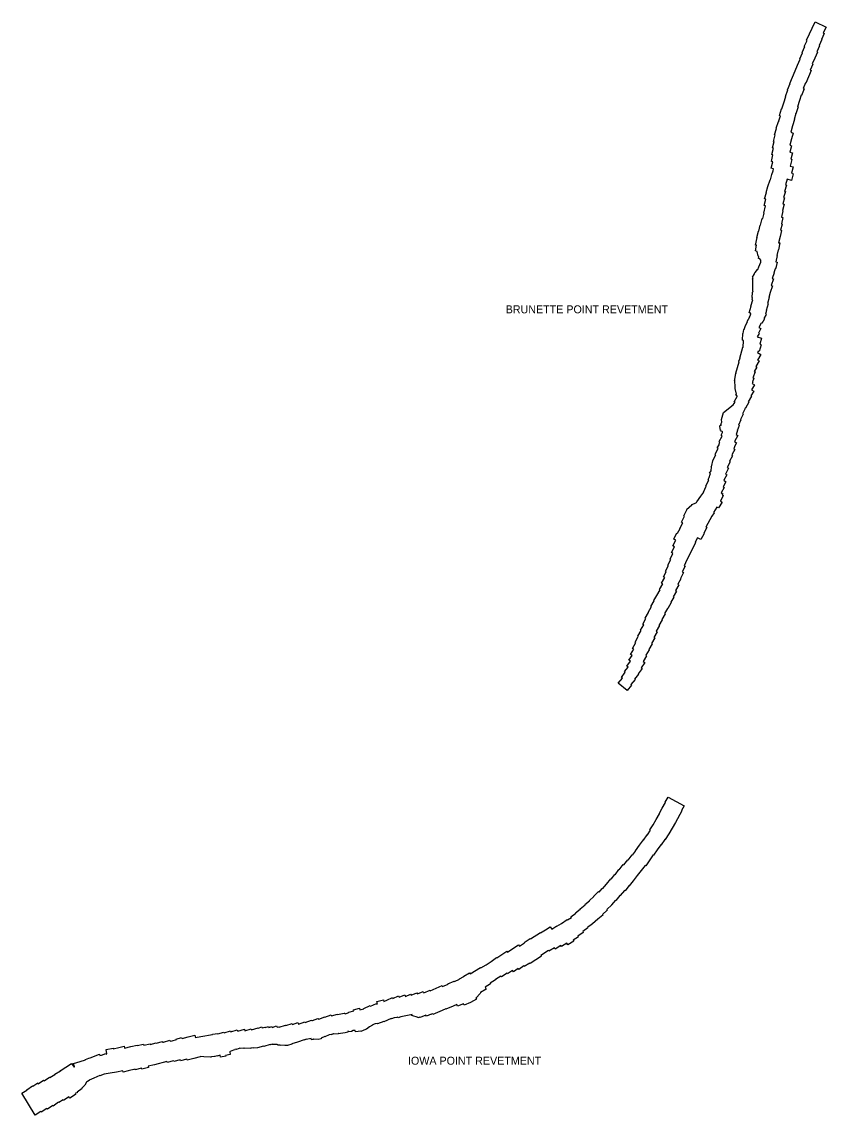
# Model space of a CAD drawing. Extents: x 2650582 to 3923188, y 277893 to 989177.
# Drawn here: x 3203021 to 3219097, y 825723 to 847578 of the extents above; entities that cross this region are included whole.
import ezdxf

# ---------------------------------------------------------------- set-up
doc = ezdxf.new("R2010")
doc.units = 0
doc.layers.add('Level 3', color=7, linetype='Continuous')

msp = doc.modelspace()

# ---------------------------------------------------------------- linework, layer by layer
at = {"layer": 'Level 3'}
for points in [[(3218284, 846087), (3218329, 846216), (3218328, 846216), (3218377, 846343), (3218369, 846346), (3218424, 846475), (3218425, 846475), (3218478, 846596), (3218480, 846596), (3218528, 846709), (3218525, 846710), (3218579, 846835), (3218570, 846840), (3218626, 846959), (3218615, 846964), (3218671, 847084), (3218661, 847088), (3218717, 847208), (3218706, 847213), (3218765, 847341), (3218768, 847339), (3218820, 847450), (3218817, 847451), (3218877, 847578), (3219097, 847475), (3219041, 847356), (3219060, 847346), (3219005, 847228), (3219012, 847224), (3218956, 847104), (3218968, 847099), (3218913, 846979), (3218926, 846974), (3218870, 846854), (3218874, 846852), (3218820, 846736), (3218832, 846730), (3218781, 846609), (3218797, 846603), (3218746, 846481), (3218746, 846481), (3218692, 846352), (3218682, 846356), (3218637, 846247), (3218655, 846240), (3218606, 846109), (3218598, 846112), (3218562, 846005)], [(3218038, 844603), (3218048, 844640), (3218000, 844653), (3218034, 844780), (3218002, 844789), (3218035, 844917), (3218009, 844924), (3218042, 845052), (3218024, 845057), (3218058, 845184), (3218045, 845187), (3218079, 845319), (3218068, 845321), (3218107, 845448), (3218100, 845450), (3218142, 845583), (3218147, 845582), (3218183, 845699), (3218168, 845704), (3218208, 845838), (3218213, 845837), (3218251, 845962), (3218252, 845962), (3218289, 846085), (3218284, 846087)], [(3218562, 846005), (3218564, 846005), (3218527, 845879), (3218535, 845876), (3218494, 845742), (3218491, 845743), (3218456, 845626), (3218465, 845623), (3218426, 845497), (3218427, 845497), (3218389, 845371), (3218437, 845356), (3218402, 845238), (3218406, 845237), (3218372, 845110), (3218407, 845100), (3218373, 844972), (3218424, 844958), (3218390, 844830), (3218413, 844824), (3218379, 844696), (3218437, 844681), (3218404, 844553), (3218441, 844543), (3218405, 844408), (3218321, 844431)], [(3217790, 842811), (3217771, 842844), (3217747, 842850), (3217753, 842881), (3217744, 842892), (3217739, 842891), (3217718, 842990), (3217683, 842998), (3217708, 843111), (3217687, 843115), (3217718, 843264), (3217712, 843265), (3217745, 843395), (3217753, 843393), (3217782, 843512), (3217786, 843511), (3217820, 843649), (3217831, 843647), (3217856, 843752), (3217849, 843753), (3217885, 843899), (3217858, 843907), (3217891, 844033), (3217864, 844041), (3217903, 844165), (3217896, 844167), (3217935, 844287), (3217933, 844288), (3217978, 844423), (3217982, 844421), (3218013, 844524), (3218012, 844524), (3218038, 844603)], [(3218321, 844431), (3218288, 844318), (3218308, 844311), (3218267, 844190), (3218284, 844184), (3218246, 844067), (3218268, 844060), (3218230, 843941), (3218258, 843933), (3218224, 843806), (3218235, 843803), (3218203, 843677), (3218235, 843669), (3218204, 843541), (3218219, 843537), (3218188, 843413), (3218207, 843408), (3218177, 843285), (3218177, 843285), (3218146, 843163), (3218173, 843158), (3218145, 843020), (3218137, 843021), (3218112, 842909), (3218120, 842907), (3218091, 842781), (3218118, 842775), (3218098, 842688)], [(3217561, 841761), (3217597, 841893), (3217593, 841894), (3217629, 842022), (3217616, 842025), (3217627, 842064), (3217620, 842065), (3217628, 842170), (3217636, 842199), (3217632, 842199), (3217635, 842435), (3217628, 842437), (3217639, 842469), (3217628, 842475), (3217656, 842529), (3217659, 842527), (3217674, 842569), (3217680, 842567), (3217680, 842567), (3217727, 842629), (3217731, 842627), (3217750, 842684), (3217754, 842683), (3217791, 842776), (3217789, 842811), (3217790, 842811)], [(3218098, 842688), (3218099, 842688), (3218096, 842681), (3218087, 842641), (3218081, 842642), (3218049, 842564), (3218056, 842559), (3218019, 842448), (3218043, 842439), (3217997, 842308), (3218023, 842300), (3217978, 842166), (3217950, 842069), (3217957, 842067), (3217923, 841947), (3217938, 841943), (3217900, 841811), (3217905, 841810), (3217885, 841736)], [(3217010, 839577), (3217007, 839627), (3217048, 839767), (3217047, 839768), (3217240, 839923), (3217276, 839975), (3217259, 839985), (3217319, 840087), (3217316, 840101), (3217294, 840114), (3217307, 840137), (3217281, 840248), (3217286, 840249), (3217276, 840249), (3217276, 840275), (3217274, 840276), (3217276, 840279), (3217275, 840404), (3217265, 840410), (3217275, 840427), (3217275, 840437), (3217275, 840437), (3217289, 840546), (3217295, 840545), (3217301, 840557), (3217295, 840558), (3217359, 840784), (3217350, 840790), (3217352, 840794), (3217379, 840856), (3217374, 840857), (3217431, 841072), (3217442, 841069), (3217444, 841206), (3217433, 841210), (3217435, 841216), (3217426, 841217), (3217435, 841351), (3217440, 841351), (3217453, 841427), (3217462, 841426), (3217458, 841428), (3217482, 841490), (3217476, 841493), (3217524, 841584), (3217520, 841586), (3217571, 841678), (3217564, 841681), (3217589, 841731), (3217583, 841733), (3217589, 841753), (3217561, 841761)], [(3217885, 841736), (3217896, 841730), (3217853, 841647), (3217864, 841642), (3217814, 841546), (3217802, 841553), (3217753, 841465), (3217790, 841446), (3217743, 841354), (3217756, 841347), (3217719, 841279)], [(3217719, 841279), (3217803, 841255)], [(3217803, 841255), (3217769, 841133), (3217800, 841124), (3217761, 840987), (3217738, 840993)], [(3217738, 840993), (3217725, 840969), (3217794, 840926), (3217727, 840818), (3217759, 840799), (3217691, 840690), (3217712, 840677), (3217661, 840591), (3217678, 840585), (3217634, 840459), (3217649, 840454), (3217623, 840380), (3217634, 840374), (3217618, 840346)], [(3217618, 840346), (3217663, 840319), (3217605, 840224), (3217650, 840197), (3217592, 840101), (3217606, 840093), (3217542, 839983), (3217555, 839975), (3217483, 839853), (3217478, 839856), (3217470, 839841), (3217475, 839838), (3217424, 839745), (3217440, 839734), (3217386, 839628), (3217395, 839622), (3217345, 839516), (3217356, 839506), (3217338, 839458)], [(3216813, 838708), (3216830, 838806), (3216834, 838805), (3216831, 838807), (3216891, 838923), (3216881, 838929), (3216884, 838934), (3216880, 838936), (3216941, 839050), (3216921, 839062), (3216956, 839121), (3216966, 839171), (3216971, 839184), (3216960, 839191), (3217022, 839299), (3216997, 839314), (3217028, 839369), (3217028, 839385), (3217019, 839388), (3217018, 839390), (3216993, 839399), (3216996, 839407), (3216985, 839406), (3216974, 839493), (3216980, 839515), (3217002, 839518), (3217006, 839528), (3216993, 839533), (3217010, 839577)], [(3217338, 839458), (3217341, 839457), (3217323, 839420), (3217320, 839413), (3217327, 839410), (3217298, 839329), (3217331, 839311), (3217267, 839186), (3217307, 839165), (3217275, 839104), (3217252, 839041), (3217271, 839031), (3217222, 838939), (3217211, 838912), (3217227, 838904), (3217169, 838793)], [(3217169, 838793), (3217182, 838785), (3217119, 838668), (3217145, 838653), (3217083, 838539), (3217111, 838524), (3217053, 838419), (3217095, 838384), (3217041, 838280), (3217057, 838272), (3217001, 838160), (3217035, 838144), (3217022, 838117)], [(3216650, 838176), (3216645, 838179), (3216702, 838296), (3216694, 838300), (3216751, 838414), (3216743, 838416), (3216746, 838424), (3216737, 838428), (3216758, 838469), (3216776, 838533), (3216777, 838533), (3216783, 838545), (3216767, 838554), (3216796, 838606), (3216808, 838681), (3216801, 838686), (3216813, 838708)], [(3216507, 837970), (3216515, 837981), (3216592, 838096), (3216596, 838094), (3216650, 838176)], [(3216176, 837449), (3216236, 837563), (3216205, 837580), (3216265, 837696), (3216250, 837704), (3216313, 837821), (3216307, 837828), (3216411, 837923), (3216409, 837925), (3216507, 837970)], [(3217022, 838117), (3217039, 838108), (3216986, 837996), (3217019, 837974), (3216943, 837860), (3216915, 837878), (3216843, 837772), (3216858, 837761), (3216810, 837695)], [(3216810, 837695), (3216693, 837479), (3216712, 837469), (3216652, 837355), (3216659, 837351), (3216594, 837229), (3216525, 837266)], [(3215660, 836007), (3215656, 836009), (3215716, 836112), (3215714, 836112), (3215779, 836225), (3215767, 836232), (3215832, 836345), (3215808, 836358), (3215873, 836471), (3215846, 836486), (3215903, 836586), (3215888, 836594), (3215946, 836708), (3215935, 836714), (3215995, 836829), (3215977, 836839), (3216036, 836953), (3216009, 836967), (3216069, 837083), (3216032, 837102), (3216091, 837216), (3216051, 837236), (3216115, 837361), (3216129, 837354), (3216178, 837449), (3216176, 837449)], [(3216525, 837266), (3216479, 837176), (3216489, 837171), (3216431, 837056), (3216433, 837055), (3216315, 836823), (3216316, 836823), (3216257, 836707), (3216278, 836696), (3216219, 836583), (3216244, 836570), (3216185, 836453), (3216196, 836446), (3216131, 836334), (3216150, 836323), (3216085, 836210), (3216107, 836197), (3216042, 836086), (3216053, 836079), (3215993, 835976), (3216001, 835971)], [(3216001, 835971), (3215930, 835851), (3215924, 835853), (3215864, 835749), (3215877, 835741), (3215813, 835630), (3215820, 835625), (3215756, 835514), (3215766, 835508), (3215702, 835397), (3215721, 835384), (3215656, 835272), (3215670, 835264), (3215605, 835151), (3215621, 835142), (3215555, 835028), (3215557, 835027), (3215492, 834915), (3215507, 834906), (3215441, 834792), (3215471, 834772), (3215397, 834665), (3215417, 834650), (3215341, 834547), (3215349, 834540), (3215268, 834439), (3215277, 834431), (3215195, 834330), (3215210, 834319), (3215121, 834210), (3214941, 834356), (3215024, 834456), (3215005, 834472), (3215081, 834577), (3215068, 834589), (3215140, 834677), (3215113, 834697), (3215185, 834796), (3215154, 834816), (3215218, 834911), (3215186, 834929), (3215251, 835041), (3215229, 835054), (3215296, 835168), (3215278, 835178), (3215343, 835290), (3215333, 835296), (3215399, 835408), (3215387, 835415), (3215452, 835527), (3215430, 835540), (3215494, 835650), (3215480, 835659), (3215545, 835770), (3215539, 835774), (3215605, 835888), (3215595, 835893), (3215660, 836007)], [(3214794, 830444), (3214800, 830440), (3214872, 830535), (3214881, 830529), (3214956, 830631), (3214958, 830630), (3215037, 830735), (3215053, 830724), (3215133, 830829), (3215142, 830823), (3215219, 830924), (3215228, 830917), (3215288, 831003), (3215284, 831006), (3215365, 831120), (3215368, 831117), (3215444, 831224), (3215446, 831222), (3215520, 831327), (3215524, 831325), (3215585, 831418), (3215573, 831426), (3215640, 831529), (3215703, 831632), (3215702, 831633), (3215764, 831747), (3215763, 831747), (3215823, 831858), (3215887, 831976), (3215883, 831978), (3215939, 832082), (3216258, 831907), (3216204, 831810), (3216214, 831805), (3216085, 831571), (3216083, 831572), (3216020, 831457), (3216017, 831458), (3215951, 831348), (3215952, 831347), (3215877, 831230), (3215871, 831233), (3215801, 831124), (3215792, 831129), (3215723, 831029), (3215648, 830922), (3215642, 830926), (3215491, 830707), (3215480, 830715), (3215402, 830611), (3215398, 830614), (3215321, 830513), (3215319, 830514), (3215240, 830408), (3215238, 830410), (3215159, 830305), (3215155, 830308), (3215079, 830204)], [(3213612, 829444), (3213713, 829507), (3213717, 829499), (3213808, 829554), (3213806, 829556), (3213923, 829633), (3213929, 829625), (3214005, 829677), (3213996, 829690), (3214093, 829761), (3214086, 829770), (3214181, 829842), (3214178, 829845), (3214279, 829928), (3214275, 829933), (3214366, 830009), (3214364, 830011), (3214454, 830092), (3214449, 830097), (3214550, 830193), (3214561, 830182), (3214623, 830254), (3214630, 830248), (3214707, 830339), (3214708, 830339), (3214794, 830444)], [(3215079, 830204), (3215064, 830215), (3214977, 830111), (3214976, 830112), (3214894, 830014), (3214886, 830019), (3214808, 829927), (3214811, 829924), (3214715, 829832), (3214723, 829822), (3214625, 829734), (3214635, 829723), (3214535, 829641), (3214537, 829638), (3214429, 829548), (3214427, 829550), (3214327, 829472), (3214332, 829466), (3214231, 829394), (3214242, 829377), (3214137, 829303), (3214146, 829290), (3214042, 829222), (3214053, 829204), (3213935, 829130), (3213917, 829159), (3213806, 829091), (3213794, 829111), (3213683, 829043), (3213666, 829070), (3213554, 829001), (3213547, 829013)], [(3212836, 829054), (3212949, 829127), (3212968, 829099), (3213071, 829166), (3213064, 829177), (3213184, 829254), (3213190, 829245), (3213386, 829373), (3213391, 829366), (3213486, 829430), (3213489, 829427), (3213582, 829490), (3213612, 829444)], [(3211419, 828316), (3211428, 828295), (3211540, 828343), (3211538, 828349), (3211663, 828403), (3211666, 828396), (3211770, 828440), (3211766, 828450), (3211855, 828496), (3211852, 828504), (3211968, 828568), (3211979, 828549), (3212190, 828675), (3212193, 828670), (3212299, 828731), (3212302, 828727), (3212403, 828792), (3212401, 828796), (3212511, 828872), (3212516, 828865), (3212712, 829003), (3212726, 828983), (3212836, 829055), (3212836, 829054)], [(3213547, 829013), (3213394, 828915), (3213405, 828898), (3213179, 828752), (3213172, 828764), (3213062, 828695), (3213055, 828707)], [(3213055, 828707), (3212953, 828637), (3212940, 828653), (3212847, 828589), (3212828, 828613), (3212731, 828547), (3212719, 828563), (3212606, 828488), (3212598, 828498), (3212489, 828432), (3212491, 828428), (3212381, 828360), (3212389, 828348), (3212279, 828280), (3212302, 828242), (3212188, 828174), (3212190, 828171), (3212182, 828166), (3212191, 828159), (3212097, 828059), (3212107, 828040), (3211989, 827976), (3211860, 827920), (3211847, 827950), (3211728, 827901), (3211714, 827932), (3211644, 827904), (3211645, 827902), (3211497, 827843), (3211495, 827847), (3211423, 827817), (3211237, 827733)], [(3210688, 828098), (3210792, 828143), (3210802, 828123), (3210917, 828171), (3210928, 828145), (3211045, 828195), (3211057, 828169), (3211179, 828221), (3211185, 828207), (3211419, 828316)], [(3209859, 827851), (3209858, 827854), (3209986, 827912), (3209991, 827903), (3210109, 827955), (3210116, 827944), (3210129, 827950), (3210116, 827993), (3210247, 828031), (3210259, 827993), (3210319, 828019), (3210318, 828022), (3210432, 828072), (3210439, 828058), (3210551, 828107), (3210564, 828079), (3210674, 828128), (3210688, 828098)], [(3208540, 827574), (3208552, 827543), (3208679, 827589), (3208685, 827576), (3208808, 827621), (3208813, 827610), (3208818, 827612), (3208818, 827613), (3208828, 827615), (3208939, 827657), (3208942, 827646), (3208953, 827649), (3208954, 827644), (3209075, 827691), (3209079, 827682), (3209200, 827729), (3209207, 827711), (3209332, 827740), (3209333, 827737), (3209460, 827762), (3209461, 827759), (3209473, 827764), (3209480, 827751), (3209503, 827755), (3209555, 827776), (3209554, 827782), (3209657, 827806), (3209651, 827828), (3209771, 827860), (3209779, 827829), (3209859, 827851)], [(3210820, 827735), (3210796, 827727), (3210593, 827691), (3210543, 827670), (3210538, 827681), (3210518, 827673), (3210516, 827678), (3210464, 827669), (3210410, 827646), (3210406, 827655), (3210256, 827590), (3210253, 827598), (3210132, 827545), (3210123, 827558), (3210081, 827546), (3210081, 827548), (3210029, 827526), (3210032, 827520), (3209967, 827485), (3209912, 827442), (3209889, 827432), (3209889, 827434), (3209797, 827394), (3209794, 827403), (3209688, 827386), (3209682, 827418), (3209646, 827412), (3209609, 827398), (3209552, 827390), (3209550, 827399), (3209532, 827392), (3209534, 827381), (3209485, 827371), (3209485, 827370), (3209389, 827352), (3209388, 827356), (3209352, 827351), (3209351, 827354), (3209342, 827353), (3209343, 827347), (3209251, 827339), (3209252, 827349), (3209245, 827347), (3209205, 827331), (3209202, 827336), (3209164, 827326), (3209075, 827290), (3209074, 827292), (3209004, 827262), (3209006, 827248), (3208944, 827234), (3208943, 827236), (3208846, 827240), (3208847, 827244), (3208810, 827230), (3208801, 827253), (3208703, 827233), (3208702, 827239), (3208663, 827224), (3208661, 827229), (3208532, 827182)], [(3211237, 827733), (3211231, 827748), (3211201, 827737), (3211199, 827743), (3211106, 827704), (3211098, 827722), (3210982, 827673), (3210979, 827679), (3210943, 827670), (3210942, 827673), (3210813, 827712), (3210820, 827735)], [(3206938, 827349), (3207058, 827384), (3207064, 827370), (3207193, 827411), (3207201, 827390), (3207327, 827431), (3207337, 827400), (3207469, 827440), (3207480, 827408), (3207607, 827447), (3207614, 827427), (3207742, 827468), (3207744, 827464), (3207817, 827488), (3207825, 827466), (3207880, 827483), (3207884, 827472), (3207951, 827492), (3207959, 827473), (3208018, 827492), (3208024, 827477), (3208113, 827505), (3208121, 827482), (3208159, 827491), (3208162, 827481), (3208292, 827522), (3208294, 827515), (3208422, 827556), (3208429, 827537), (3208540, 827574)], [(3204721, 826948), (3204708, 827038), (3204847, 827059), (3204848, 827051), (3204959, 827074), (3205063, 827100), (3205072, 827064), (3205199, 827096), (3205326, 827122), (3205327, 827115), (3205454, 827142), (3205459, 827120), (3205586, 827147), (3205588, 827137), (3205705, 827166), (3205706, 827163), (3205831, 827194), (3205834, 827180), (3205847, 827184), (3205849, 827180), (3205978, 827223), (3205986, 827200), (3206025, 827210), (3206109, 827238), (3206108, 827243), (3206210, 827275), (3206216, 827259), (3206222, 827260), (3206223, 827257), (3206343, 827287), (3206342, 827291), (3206478, 827325), (3206490, 827276)], [(3206490, 827276), (3206596, 827297), (3206597, 827293), (3206834, 827336), (3206833, 827339), (3206936, 827358), (3206938, 827349)], [(3208532, 827182), (3208418, 827147), (3208420, 827142), (3208329, 827112), (3208327, 827117), (3208276, 827117), (3208276, 827113), (3208200, 827120), (3208175, 827115), (3208174, 827122), (3208137, 827125), (3208138, 827130), (3208129, 827127), (3208126, 827133), (3208025, 827135), (3208025, 827139), (3207990, 827128), (3207985, 827137), (3207857, 827094), (3207852, 827105), (3207729, 827069), (3207728, 827071), (3207658, 827062), (3207658, 827066), (3207606, 827061), (3207606, 827065), (3207585, 827057), (3207581, 827062), (3207471, 827056), (3207470, 827060), (3207445, 827053), (3207441, 827064), (3207381, 827056), (3207380, 827063), (3207308, 827038), (3207306, 827042), (3207281, 827033), (3207282, 827027), (3207250, 827021), (3207183, 826996), (3207184, 826993), (3207177, 826991), (3207187, 826933), (3207092, 826917), (3207095, 826899), (3206988, 826884), (3206982, 826919), (3206925, 826902), (3206923, 826907), (3206875, 826893), (3206874, 826895), (3206808, 826887), (3206808, 826889), (3206795, 826884), (3206794, 826881), (3206656, 826891), (3206655, 826888), (3206584, 826896)], [(3204073, 826688), (3204054, 826755), (3204184, 826796), (3204185, 826792), (3204293, 826828), (3204290, 826837), (3204360, 826859), (3204386, 826871), (3204573, 826941), (3204581, 826917), (3204613, 826924), (3204613, 826924), (3204700, 826958), (3204704, 826945), (3204721, 826948)], [(3206584, 826896), (3206586, 826889), (3206458, 826857), (3206459, 826853), (3206323, 826819), (3206318, 826840), (3206189, 826808), (3206185, 826829), (3206056, 826797), (3206054, 826808), (3205925, 826777), (3205921, 826794), (3205674, 826732)], [(3203021, 826165), (3203122, 826225), (3203118, 826232), (3203235, 826308), (3203240, 826300), (3203338, 826367), (3203349, 826351), (3203455, 826425), (3203466, 826411), (3203572, 826485), (3203580, 826474), (3203682, 826537), (3203680, 826540), (3203790, 826609), (3203789, 826611), (3203899, 826680), (3203897, 826683), (3204016, 826757), (3204063, 826682), (3204073, 826688)], [(3205674, 826732), (3205675, 826726), (3205548, 826699), (3205553, 826673), (3205416, 826644), (3205413, 826659), (3205286, 826632), (3205284, 826644), (3205146, 826609), (3205047, 826584), (3205041, 826611), (3204915, 826583), (3204785, 826565), (3204785, 826562), (3204665, 826545), (3204581, 826508), (3204579, 826513), (3204460, 826460), (3204459, 826463), (3204364, 826420), (3204366, 826416), (3204332, 826397)], [(3204332, 826397), (3204310, 826380), (3204278, 826324), (3204219, 826260), (3204223, 826254), (3204129, 826181), (3204131, 826175), (3204086, 826153)], [(3204086, 826153), (3204095, 826137), (3203977, 826063), (3203962, 826087), (3203852, 826018), (3203843, 826032), (3203759, 825973), (3203755, 825980), (3203649, 825905), (3203639, 825919), (3203532, 825844), (3203523, 825858), (3203409, 825784), (3203403, 825793), (3203286, 825723), (3203021, 826165)]]:
    msp.add_lwpolyline(points, dxfattribs=at)

# ---------------------------------------------------------------- texts
for s, p in [('BRUNETTE POINT REVETMENT', (3212692, 841751)), ('IOWA POINT REVETMENT', (3210739, 826731))]:
    msp.add_text(s, height=160, dxfattribs=at).set_placement(p)

doc.saveas('drawing.dxf')
